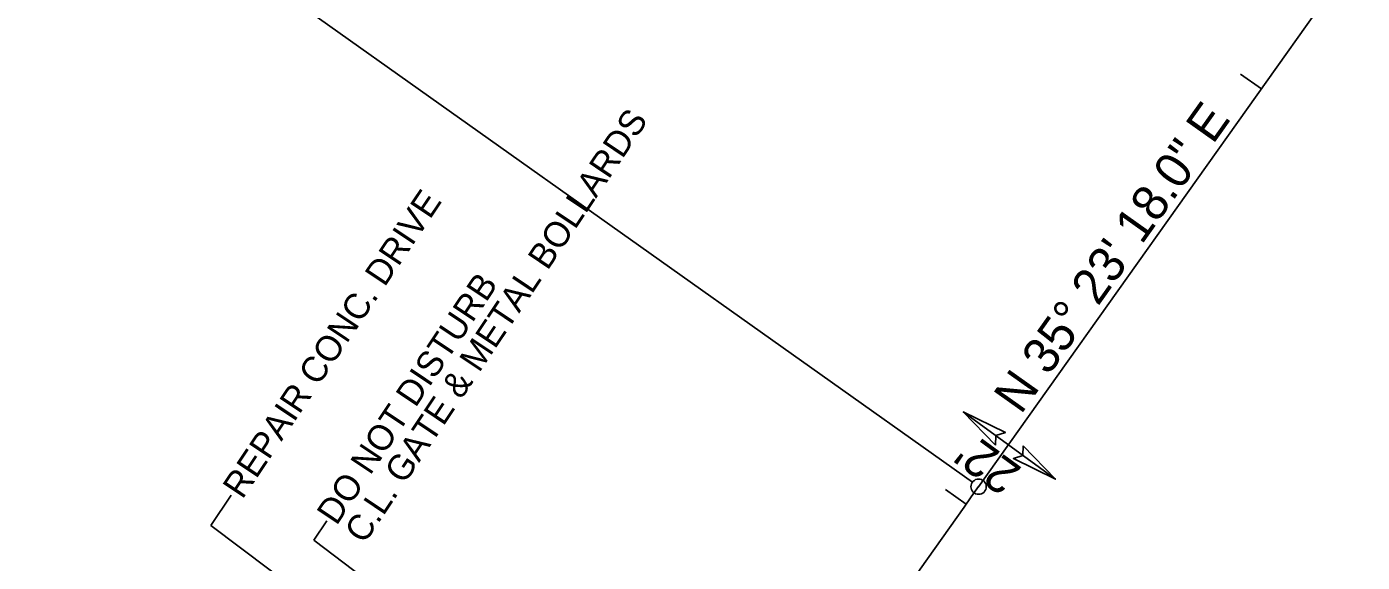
# Model space of a CAD drawing. Extents: x 1716813 to 1718091, y 800228 to 801730.
# Drawn here: x 1717558 to 1717820.1, y 801328.1 to 801433.3 of the extents above; entities that cross this region are included whole.
import ezdxf

# ---------------------------------------------------------------- set-up
doc = ezdxf.new("R2010")
doc.units = 0
for name, color, linetype in [('Prop Dimension', 7, 'Continuous'), ('Prop DSN Text', 7, 'Continuous'), ('Prop Horizontal Alignment', 7, 'Continuous'), ('Prop Horizontal Alignment Direction Label', 7, 'Continuous'), ('Prop Horizontal Alignment Station Label', 7, 'Continuous'), ('Prop Horizontal Alignment Tick Small', 7, 'Continuous'), ('Prop Terminator CELL', 7, 'Continuous')]:
    doc.layers.add(name, color=color, linetype=linetype)

msp = doc.modelspace()

# ---------------------------------------------------------------- linework, layer by layer
at = {"layer": 'Prop Dimension'}
msp.add_line((1717759.89, 801344.43), (1717741.8, 801357.67), dxfattribs=at)
at = {"layer": 'Prop DSN Text'}
for p, q in [((1717598.14, 801341.28), (1717594.17, 801335.36)), ((1717594.17, 801335.36), (1717653.56, 801290.68)), ((1717616.9, 801336.26), (1717614.37, 801332.47)), ((1717614.37, 801332.47), (1717628.62, 801321.71))]:
    msp.add_line(p, q, dxfattribs=at)
at = {"layer": 'Prop Horizontal Alignment'}
msp.add_line((1717744.81, 801342.98), (1717820.08, 801448.95), dxfattribs=at)
msp.add_arc((1722391.71, 798042.03), 5700, 144.61167, 146.20506, dxfattribs=at)
at = {"layer": 'Prop Horizontal Alignment Station Label'}
msp.add_line((1717743.58, 801343.85), (1717520.61, 801502.24), dxfattribs=at)
msp.add_circle((1717744.81, 801342.98), 1.5, dxfattribs=at)
at = {"layer": 'Prop Horizontal Alignment Tick Small'}
for p, q in [((1717800.28, 801421.07), (1717796.2, 801423.97)), ((1717742.37, 801339.55), (1717738.29, 801342.44))]:
    msp.add_line(p, q, dxfattribs=at)
at = {"layer": 'Prop Terminator CELL'}
for points in [[(1717748.15, 801351.1), (1717741.8, 801357.67), (1717750.05, 801353.62), (1717748.17, 801353)], [(1717753.54, 801351), (1717759.89, 801344.43), (1717751.64, 801348.48), (1717753.51, 801349.09)]]:
    msp.add_lwpolyline(points, close=True, dxfattribs=at)

# ---------------------------------------------------------------- texts
at = {"layer": 'Prop Dimension'}
msp.add_text("22'", height=7, rotation=143.7823, dxfattribs=at).set_placement((1717753.54, 801346.53))
at = {"layer": 'Prop DSN Text'}
for s, p in [('C.L. GATE & METAL BOLLARDS', (1717624.27, 801331.55)), ('REPAIR CONC. DRIVE', (1717600.36, 801340.35)), ('DO NOT DISTURB', (1717618.82, 801335.19))]:
    msp.add_text(s, height=5, rotation=56.2051, dxfattribs=at).set_placement(p)
at = {"layer": 'Prop Horizontal Alignment Direction Label'}
msp.add_text('N 35%%d 23\' 18.0" E', height=7, rotation=54.6117, dxfattribs=at).set_placement((1717753.09, 801356.98))

doc.saveas('drawing.dxf')
